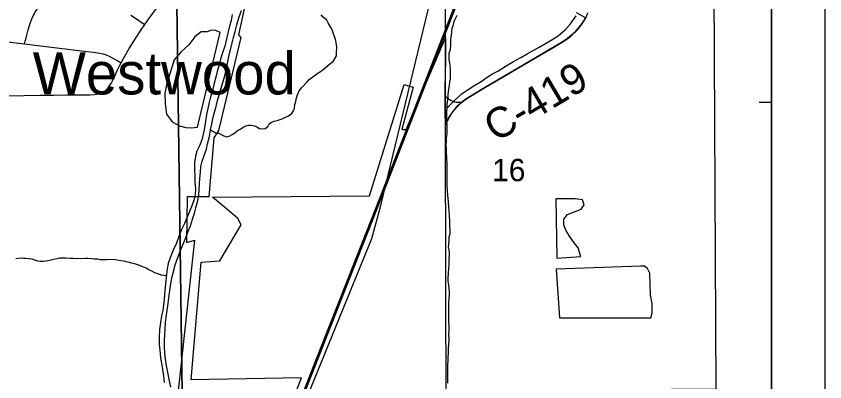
# Model space of a CAD drawing. Extents: x 0 to 34, y 0 to 22.
# Drawn here: x 7.485 to 9, y 18.904 to 19.588 of the extents above; entities that cross this region are included whole.
import ezdxf

# ---------------------------------------------------------------- set-up
doc = ezdxf.new("R2010")
doc.units = 0
for name, color, linetype in [('Default', 7, 'Continuous'), ('GM_X_County_Road', 7, 'Continuous'), ('GM_X_County_Road_Text', 7, 'Continuous'), ('GM_X_Major_River', 7, 'Continuous'), ('GM_X_Minor_Lake', 7, 'Continuous'), ('GM_X_Minor_River', 7, 'Continuous'), ('GM_X_Rail_Line', 7, 'Continuous'), ('GM_X_Section', 7, 'Continuous'), ('GM_X_Section_Text', 7, 'Continuous'), ('GM_X_State_Route', 7, 'Continuous'), ('GM_X_Township_Road', 7, 'Continuous'), ('GM_X_Unincorporated_Text', 7, 'Continuous'), ('SH_Data', 7, 'Continuous')]:
    doc.layers.add(name, color=color, linetype=linetype)

msp = doc.modelspace()

# ---------------------------------------------------------------- linework, layer by layer
at = {"layer": 'Default'}
msp.add_lwpolyline([(8.9, 18.8897), (8.9, 19.8895), (8.7909, 19.8887), (8.796, 18.8901)], close=True, dxfattribs=at)
for points in [[(7.93, 19.6856), (7.9016, 19.5536), (7.9059, 19.5483), (7.864, 19.3745), (7.8556, 19.3606), (7.8461, 19.2501), (7.8055, 19.2502), (7.804, 19.165), (7.8191, 19.1693), (7.7881, 18.8817)], [(8.0085, 18.8827), (8.0194, 18.9112), (7.8126, 18.9077), (7.8317, 19.1282), (7.8664, 19.1302), (7.9065, 19.1977), (7.9004, 19.2098), (7.883, 19.2247), (7.8526, 19.2498), (8.1472, 19.2519), (8.2117, 19.4603), (8.2285, 19.4555), (8.2077, 19.376), (8.2159, 19.376), (8.2894, 19.5481), (8.2888, 19.4393), (8.2892, 19.3852), (8.2965, 19.4001), (8.3114, 19.4199), (8.3199, 19.428), (8.3202, 19.4282), (8.3273, 19.4336), (8.3403, 19.4419), (8.3644, 19.4559), (8.391, 19.4717), (8.4471, 19.5047), (8.4932, 19.5317), (8.5078, 19.5406), (8.5182, 19.5474), (8.5257, 19.5533), (8.533, 19.5599), (8.5362, 19.5634), (8.5394, 19.567), (8.5429, 19.5713), (8.5452, 19.5746), (8.5486, 19.5795), (8.5518, 19.5851), (8.5345, 19.5944)]]:
    msp.add_lwpolyline(points, dxfattribs=at)
at = {"layer": 'GM_X_County_Road'}
for points in [[(8.2891, 19.5786), (8.2891, 19.5847), (8.2892, 19.6066), (8.2896, 19.6316), (8.2894, 19.6438), (8.29, 19.6938), (8.2898, 19.7157), (8.2899, 19.7375), (8.2899, 19.7527), (8.29, 19.7634)], [(8.5516, 19.5837), (8.552, 19.5845), (8.5563, 19.5945)], [(8.2896, 19.5475), (8.2894, 19.5528), (8.2892, 19.5715), (8.2891, 19.5786)], [(8.3202, 19.4274), (8.3275, 19.433), (8.3405, 19.4413), (8.3646, 19.4554), (8.3912, 19.4712), (8.4473, 19.5041), (8.4935, 19.5311), (8.5081, 19.54), (8.5184, 19.5468), (8.5259, 19.5527), (8.5332, 19.5593), (8.5364, 19.5629), (8.5396, 19.5664), (8.5431, 19.5708), (8.5455, 19.574), (8.5488, 19.579), (8.5516, 19.5837)], [(8.289, 19.4388), (8.2892, 19.4935), (8.2891, 19.5278), (8.2896, 19.5475)], [(8.2895, 19.3846), (8.289, 19.4094), (8.289, 19.4388)], [(8.289, 19.4388), (8.2944, 19.4345), (8.297, 19.4324), (8.2999, 19.4307), (8.3029, 19.4293), (8.306, 19.4283), (8.3093, 19.4276), (8.3116, 19.4273), (8.3155, 19.4272), (8.3202, 19.4274)], [(8.2895, 19.3846), (8.2968, 19.3996), (8.3002, 19.4049), (8.3057, 19.4123), (8.3116, 19.4194), (8.3155, 19.4236), (8.3202, 19.4274)], [(8.2911, 18.8456), (8.2907, 18.906), (8.2905, 18.9401), (8.29, 19.0082), (8.2898, 19.0423), (8.2899, 19.0857), (8.2898, 19.1136), (8.2897, 19.1353), (8.29, 19.1539), (8.2902, 19.2096), (8.2895, 19.2654), (8.2896, 19.315), (8.2896, 19.3521), (8.2895, 19.3846)]]:
    msp.add_lwpolyline(points, dxfattribs=at)
at = {"layer": 'GM_X_Major_River'}
for points in [[(7.8894, 19.5918), (7.8876, 19.5801), (7.8843, 19.5672), (7.8758, 19.5322), (7.8714, 19.5197), (7.8676, 19.5079), (7.8647, 19.4953), (7.8617, 19.4851), (7.8588, 19.4744), (7.8558, 19.463), (7.8533, 19.4516), (7.8488, 19.4372), (7.8466, 19.4273), (7.844, 19.4155), (7.8419, 19.4041), (7.84, 19.3916), (7.8379, 19.3791), (7.8353, 19.3673), (7.8331, 19.357), (7.8282, 19.346), (7.8238, 19.3357), (7.8208, 19.3262), (7.819, 19.3148), (7.8191, 19.3008), (7.8195, 19.2883), (7.82, 19.2781), (7.8208, 19.2652), (7.8205, 19.2542), (7.818, 19.2439), (7.8139, 19.2333), (7.8098, 19.223), (7.8053, 19.2123), (7.8001, 19.2002), (7.7941, 19.188), (7.7896, 19.1762), (7.7852, 19.1633), (7.7792, 19.1503), (7.7736, 19.1363), (7.7699, 19.1252), (7.7677, 19.1157), (7.7667, 19.1055), (7.7656, 19.093), (7.7642, 19.0812), (7.7631, 19.0679), (7.7624, 19.0577), (7.761, 19.0482), (7.7595, 19.0375), (7.7573, 19.0277), (7.7555, 19.0151), (7.7537, 19.0022), (7.7531, 18.9867), (7.7532, 18.9734), (7.754, 18.9639), (7.7556, 18.9492), (7.7584, 18.9313), (7.7608, 18.9147), (7.762, 18.9029)], [(7.7749, 18.8939), (7.7718, 18.9083), (7.7691, 18.9223), (7.7667, 18.9337), (7.7651, 18.9466), (7.7635, 18.9579), (7.763, 18.9693), (7.763, 18.9803), (7.7633, 18.9932), (7.764, 19.0027), (7.765, 19.0152), (7.7661, 19.0251), (7.7679, 19.0376), (7.7701, 19.0505), (7.7718, 19.0661), (7.7733, 19.0794), (7.7751, 19.0911), (7.7773, 19.1014), (7.7802, 19.1124), (7.7832, 19.1231), (7.788, 19.1367), (7.7944, 19.1527), (7.7992, 19.1645), (7.8037, 19.1752), (7.8074, 19.1858), (7.8119, 19.1961), (7.8156, 19.2086), (7.8193, 19.2197), (7.8218, 19.2295), (7.8255, 19.2436), (7.827, 19.2531), (7.8281, 19.2637), (7.8287, 19.2743), (7.8294, 19.2846), (7.8301, 19.2963), (7.8308, 19.3073), (7.8337, 19.3172), (7.8371, 19.3275), (7.8415, 19.3397), (7.8437, 19.3495), (7.8471, 19.3632), (7.8489, 19.3757), (7.8514, 19.386), (7.8536, 19.3966), (7.8566, 19.4084), (7.8595, 19.4191), (7.8625, 19.4308), (7.8651, 19.4411), (7.871, 19.4601), (7.874, 19.4704), (7.8769, 19.4818), (7.8795, 19.4928), (7.8817, 19.5038), (7.8839, 19.5156), (7.8894, 19.5384), (7.8924, 19.5486), (7.8953, 19.5597), (7.8986, 19.5722), (7.9023, 19.5851), (7.9072, 19.5992)]]:
    msp.add_lwpolyline(points, dxfattribs=at)
at = {"layer": 'GM_X_Minor_Lake'}
for points in [[(7.8669, 19.5575), (7.8589, 19.5617), (7.851, 19.562), (7.8431, 19.5589), (7.8317, 19.5588), (7.82, 19.5496), (7.8088, 19.5347), (7.7937, 19.521), (7.7813, 19.5065), (7.7728, 19.4802), (7.7669, 19.4597), (7.7636, 19.4434), (7.7641, 19.424), (7.7669, 19.4051), (7.7772, 19.3904), (7.7912, 19.3833), (7.803, 19.38), (7.8136, 19.3793), (7.8246, 19.3805)], [(7.8246, 19.3805), (7.8669, 19.5575)], [(8.4982, 19.1353), (8.5432, 19.1386), (8.5378, 19.1545), (8.5302, 19.1639), (8.5214, 19.1764), (8.5149, 19.1877), (8.511, 19.1972), (8.5113, 19.2082), (8.5177, 19.2169), (8.5294, 19.2216), (8.5437, 19.227), (8.549, 19.2354), (8.5459, 19.2445), (8.5322, 19.2466), (8.4963, 19.2464)], [(8.4963, 19.2464), (8.4982, 19.1353)], [(8.5031, 19.0238), (8.6739, 19.0239), (8.6765, 19.0331), (8.6768, 19.0501), (8.6732, 19.0664), (8.6727, 19.0873), (8.6722, 19.1077), (8.668, 19.116), (8.6623, 19.1202), (8.6551, 19.1205), (8.4968, 19.1148)], [(8.4968, 19.1148), (8.5031, 19.0238)]]:
    msp.add_lwpolyline(points, dxfattribs=at)
at = {"layer": 'GM_X_Minor_River'}
for points in [[(7.8488, 19.3755), (7.8597, 19.3697), (7.8647, 19.3694), (7.8693, 19.3672), (7.8743, 19.3642), (7.8792, 19.3627), (7.8838, 19.3639), (7.8894, 19.3671), (7.8947, 19.3702), (7.8992, 19.3736), (7.9049, 19.3768), (7.9098, 19.3802), (7.9151, 19.383), (7.9204, 19.3842), (7.9261, 19.3843), (7.9314, 19.3832), (7.936, 19.381), (7.941, 19.378), (7.9456, 19.3773), (7.9513, 19.3781), (7.9562, 19.382), (7.9588, 19.3866), (7.9633, 19.3901), (7.9682, 19.3917), (7.9743, 19.3933), (7.9834, 19.3964), (7.9894, 19.3995), (7.994, 19.4015), (8.0008, 19.4054), (8.0045, 19.4111), (8.0063, 19.4165), (8.007, 19.4229), (8.0088, 19.4287), (8.0099, 19.4332), (8.0121, 19.4412), (8.0154, 19.4485), (8.0195, 19.4543), (8.0304, 19.4654), (8.0341, 19.47), (8.0432, 19.4766), (8.0492, 19.4812), (8.0552, 19.4847), (8.0628, 19.4905), (8.0673, 19.4944), (8.0722, 19.4986), (8.0786, 19.5037), (8.0853, 19.5144), (8.0852, 19.5201), (8.0855, 19.5292), (8.085, 19.5353), (8.083, 19.5451), (8.081, 19.5516), (8.0787, 19.5572), (8.0774, 19.5618), (8.0739, 19.5686), (8.0697, 19.5757), (8.0669, 19.5806), (8.0604, 19.5866), (8.0565, 19.5911)], [(8.3106, 19.5896), (8.3065, 19.5812), (8.3043, 19.5758), (8.3029, 19.5701), (8.3014, 19.5651), (8.3007, 19.559), (8.2997, 19.5522), (8.299, 19.5461), (8.2987, 19.5408), (8.2988, 19.5347), (8.2978, 19.5256), (8.2959, 19.5183), (8.2956, 19.5123), (8.2957, 19.5073), (8.2969, 19.5013), (8.2974, 19.4959), (8.2978, 19.4899), (8.2983, 19.4827), (8.298, 19.4777), (8.2981, 19.4713), (8.297, 19.4656), (8.2963, 19.4595), (8.2949, 19.4522), (8.2946, 19.4473), (8.2939, 19.442), (8.2936, 19.4363), (8.2926, 19.4279), (8.2919, 19.4226), (8.2916, 19.4172), (8.2913, 19.4096)], [(8.2915, 19.4162), (8.2955, 19.4197), (8.3083, 19.4327), (8.3207, 19.4438), (8.3316, 19.4511), (8.3444, 19.4595), (8.3561, 19.4664), (8.3674, 19.4745), (8.3772, 19.4802), (8.3874, 19.4856), (8.4033, 19.4952), (8.4169, 19.5036), (8.4308, 19.511), (8.4421, 19.5179), (8.4538, 19.524), (8.4651, 19.5306), (8.4768, 19.5375), (8.4874, 19.5436), (8.5002, 19.5517), (8.5142, 19.5632), (8.5236, 19.5738), (8.5344, 19.5887)], [(8.2913, 19.4096), (8.291, 19.4028), (8.2911, 19.3899), (8.2916, 19.3846), (8.292, 19.3796), (8.2921, 19.3732), (8.2918, 19.3682), (8.2908, 19.3606), (8.2905, 19.3534), (8.2902, 19.3481), (8.2903, 19.3397), (8.2908, 19.3318), (8.2912, 19.3253), (8.2913, 19.3204), (8.2918, 19.3132), (8.2921, 19.2869), (8.2918, 19.2805), (8.2916, 19.2698), (8.2924, 19.2623), (8.2933, 19.2532), (8.2942, 19.2403), (8.2951, 19.2312), (8.2956, 19.2236), (8.2964, 19.2171), (8.2965, 19.2122), (8.2966, 19.2065), (8.2971, 19.1951), (8.2976, 19.1879), (8.2973, 19.1803), (8.2958, 19.1753), (8.2955, 19.1692), (8.2949, 19.1613), (8.2942, 19.1563), (8.2958, 19.151), (8.2962, 19.1449), (8.2956, 19.132), (8.2957, 19.1248), (8.2951, 19.1161), (8.2944, 19.1069), (8.2938, 19.0986), (8.2939, 19.0925), (8.2947, 19.0853), (8.2956, 19.0788), (8.296, 19.072), (8.2961, 19.0671), (8.2954, 19.0598), (8.2948, 19.0519), (8.295, 19.037), (8.2947, 19.0294), (8.2949, 19.0165), (8.2953, 19.0097), (8.2954, 19.0002), (8.2952, 18.9918), (8.2953, 18.9839), (8.2947, 18.9732), (8.2944, 18.9675), (8.2941, 18.9561), (8.2938, 18.9512), (8.2935, 18.9424), (8.2929, 18.9356), (8.2933, 18.9014)], [(7.7664, 19.1027), (7.7567, 19.1039), (7.7525, 19.1054), (7.7448, 19.1083), (7.7391, 19.1113), (7.7337, 19.1139), (7.7288, 19.1169), (7.7226, 19.1191), (7.7112, 19.1235), (7.7066, 19.1249), (7.7012, 19.1264), (7.6971, 19.1271), (7.691, 19.1285), (7.6871, 19.1296), (7.6814, 19.1307), (7.6742, 19.1317), (7.6666, 19.1328), (7.6555, 19.1326), (7.6517, 19.1322), (7.6468, 19.1321), (7.6422, 19.1324), (7.638, 19.1335), (7.6312, 19.1338), (7.6266, 19.1345), (7.6194, 19.1348), (7.6152, 19.1347), (7.6087, 19.1343), (7.6019, 19.1346), (7.5973, 19.1345), (7.592, 19.1348), (7.5867, 19.1347), (7.5783, 19.1354), (7.5661, 19.1352), (7.5612, 19.1344), (7.5509, 19.132), (7.5445, 19.1307), (7.5403, 19.1299), (7.5358, 19.1291), (7.5308, 19.129), (7.5255, 19.1301), (7.5201, 19.1319), (7.5152, 19.1334), (7.5095, 19.1341), (7.5026, 19.1351), (7.4988, 19.1351), (7.495, 19.1354), (7.4893, 19.1349), (7.4844, 19.1345)]]:
    msp.add_lwpolyline(points, dxfattribs=at)
at = {"layer": 'GM_X_Rail_Line'}
for points in [[(7.4155, 16.9797), (7.4558, 17.1778), (7.5178, 17.4999), (7.5426, 17.6225), (7.5717, 17.7043), (7.6321, 17.8584), (7.8825, 18.4937), (8.0236, 18.8584), (8.1515, 19.1722), (8.1675, 19.2314), (8.3282, 19.8945)], [(7.8762, 18.5116), (8.1665, 19.2479), (8.2876, 19.5584), (8.3296, 19.6662)], [(7.8783, 18.5108), (8.1687, 19.2471), (8.2898, 19.5575), (8.3318, 19.6654)]]:
    msp.add_lwpolyline(points, dxfattribs=at)
at = {"layer": 'GM_X_Section'}
for points in [[(6.7799, 19.8913), (7.782, 19.8851), (7.7959, 18.8831), (6.7847, 18.8752)], [(7.782, 19.8851), (8.7909, 19.8887), (8.796, 18.8901), (7.7959, 18.8831)]]:
    msp.add_lwpolyline(points, close=True, dxfattribs=at)
at = {"layer": 'GM_X_State_Route'}
msp.add_lwpolyline([(5.7774, 16.9797), (7.8038, 16.9797), (7.7904, 17.865), (8.296, 17.8766), (8.8033, 17.8763), (8.7984, 18.8872), (8.9, 18.8876), (8.9, 20.9), (5.6507, 20.9)], dxfattribs=at)
at = {"layer": 'GM_X_Township_Road'}
for points in [[(7.7261, 19.5729), (7.7347, 19.5853), (7.7421, 19.5953), (7.7517, 19.6075), (7.7553, 19.6126), (7.7587, 19.6177), (7.7617, 19.6232), (7.7629, 19.626), (7.7638, 19.6289), (7.7645, 19.632), (7.7648, 19.635), (7.765, 19.6381), (7.7649, 19.6404), (7.7644, 19.6434), (7.7635, 19.6464), (7.7625, 19.6493), (7.7598, 19.6549), (7.7566, 19.6603), (7.7531, 19.6654), (7.7414, 19.6798), (7.714, 19.7134), (7.7072, 19.7219)], [(7.5009, 19.5366), (7.5021, 19.5418), (7.5035, 19.5479), (7.5075, 19.5628), (7.5112, 19.5747), (7.5145, 19.5834), (7.5171, 19.589), (7.52, 19.5945), (7.5234, 19.5997), (7.5271, 19.6047), (7.533, 19.6118), (7.5394, 19.6186), (7.5439, 19.6228), (7.5512, 19.6286), (7.5614, 19.6357), (7.5693, 19.6407), (7.5814, 19.6476)], [(7.7, 19.5903), (7.7102, 19.5834), (7.7211, 19.5762), (7.7261, 19.5729)], [(7.6817, 19.5012), (7.6858, 19.5089), (7.697, 19.5277), (7.71, 19.5486), (7.7189, 19.5627), (7.7261, 19.5729)], [(7.4352, 19.5476), (7.4372, 19.5463), (7.44, 19.545), (7.4433, 19.5441), (7.4466, 19.5433), (7.4589, 19.5415), (7.5009, 19.5366)], [(7.5009, 19.5366), (7.5054, 19.5361), (7.561, 19.529), (7.6075, 19.5235), (7.6292, 19.5209), (7.6415, 19.519), (7.6476, 19.5177), (7.6535, 19.5158), (7.6593, 19.5135), (7.6648, 19.5107), (7.6757, 19.5046), (7.6817, 19.5012)], [(7.4688, 19.4394), (7.4994, 19.44), (7.5303, 19.4404), (7.555, 19.4407), (7.5798, 19.441), (7.5984, 19.4411), (7.6232, 19.4414), (7.6325, 19.4419), (7.6386, 19.4429), (7.6416, 19.4438), (7.6445, 19.4449), (7.6472, 19.446), (7.6497, 19.4475), (7.6523, 19.4495), (7.6548, 19.4516), (7.6567, 19.4537), (7.6589, 19.4562), (7.6608, 19.4592), (7.6627, 19.4623), (7.6655, 19.4674), (7.6717, 19.4807), (7.6742, 19.4866), (7.6784, 19.4953), (7.6817, 19.5012)], [(8.8772, 19.4274), (8.8876, 19.4273), (8.9, 19.4274)]]:
    msp.add_lwpolyline(points, dxfattribs=at)
at = {"layer": 'SH_Data'}
for p, q in [((9, 21), (9, 14)), ((8.9, 20.9), (8.9, 14.1))]:
    msp.add_line(p, q, dxfattribs=at)

# ---------------------------------------------------------------- texts
at = {"layer": 'GM_X_County_Road_Text'}
msp.add_text('C-419', height=0.05682, rotation=30.6922, dxfattribs=at).set_placement((8.3834, 19.3514))
at = {"layer": 'GM_X_Section_Text'}
msp.add_text('16', height=0.04186, rotation=0, dxfattribs=at).set_placement((8.3768, 19.2795))
at = {"layer": 'GM_X_Unincorporated_Text'}
msp.add_text('Westwood', height=0.07898, rotation=0, dxfattribs=at).set_placement((7.516, 19.4419))

doc.saveas('drawing.dxf')
